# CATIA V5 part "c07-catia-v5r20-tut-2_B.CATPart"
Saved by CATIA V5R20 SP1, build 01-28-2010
Part number: Part1
Bounding box of the stored display mesh (mm): x 0 to 32, y -32 to 32, z -15 to 36
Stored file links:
  D:\v5_r20\psrt_files_downloaded\c07-catia-v5r20-prt\c07-catia-v5r20-tut-2_B.CATPart
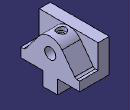
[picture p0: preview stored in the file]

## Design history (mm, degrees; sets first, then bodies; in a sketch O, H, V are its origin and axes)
Body1 (main body)
  Sketch1 on zx-plane, origin (0, 0, 0), H (-1, 0, 0), V (0, 0, 1)
    line L1 (0, 0) -> (0, 36)
    line L2 (0, 36) -> (-12, 36)
    line L3 (-12, 36) -> (-12, 10)
    line L4 (-12, 10) -> (-32, 10)
    line L5 (-32, 10) -> (-32, 0)
    point P5 (-32, 0)
    line L6 (-32, 0) -> (0, 0)
    length L1 = 36
    length L2 = 12
    length L5 = 10
    length L6 = 32
    vertical: L1 V, L3 V, L5 V
    horizontal: L2 H, L4 H, L6 H
    coincidence: P5 H
  Pad1: profile Sketch1, direction (0, 1, 0), length 32, mirrored extent
  Sketch2 on face of Pad1 from Sketch1.L5, origin (32, 0, 0), H (0, 1, 0), V (0, 0, 1)
    line L1 (0, 10) -> (27.5, 10)
    point P1 (0, 10)
    point P2 (27.5, 10)
    line L2 (27.5, 10) -> (12.8, 29.6)
    point P3 (12.8, 29.6)
    reference projected line E1 (-32, 10) -> (32, 10) from edge [face of Pad1 from Sketch1.L5 | face of Pad1 from Sketch1.L4]
    point P4 (-27.5, 10)
    point P5 (0, 10)
    line L3 (0, 10) -> (-27.5, 10)
    point P6 (-12.8, 29.6)
    line L4 (-27.5, 10) -> (-12.8, 29.6)
    arc A1 centre (0, 20) radius 16 from (12.8, 29.6) to (-12.8, 29.6) ccw
    reference projected line E2 (-32, 36) -> (32, 36) from edge [face of Pad1 from Sketch1.L3 | face of Pad1 from Sketch1.L2]
    radius A1 = 16
    distance P4 P2 = 55
    coincidence: P1 V, L1 E1, P1 P5
    horizontal: L1 H
    symmetry: P2 P4 V, P1 P5 V, L1 L3 V, P3 P6 V, L2 L4 V
    tangency: A1 L2, A1 E2
  Pad2: profile Sketch2, direction (1, 0, 0), up to the existing solid (limit type 2)
  Sketch3 on face of Pad2, origin (32, 0, 0), H (0, 1, 0), V (0, 0, 1)
    point P1 (-8, 0)
    line L1 (-8, 0) -> (8, 0)
    line L2 (8, 0) -> (8, -15)
    line L3 (8, -15) -> (-8, -15)
    line L4 (-8, -15) -> (-8, 0)
    length L3 = 16
    length L2 = 15
    distance L4 V = 8
    coincidence: P1 H
    horizontal: L1 H, L3 H
    vertical: L2 V, L4 V
  Pad3: profile Sketch3, direction (1, 0, 0), up to face of Pad1 from Sketch1.L1
  Sketch4 on zx-plane, origin (0, 0, 0), H (-1, 0, 0), V (0, 0, 1)
    point P1 (-20, 36)
    reference projected line E1 (0, 36) -> (-10, 36) from edge [face of Pad1 from Sketch1.L2 | end face of Pad1]
    distance P1 V = 20
    coincidence: P1 E1
  Sketch5 on {plane type Tangent, Support face of Pad2 from Sketch2.A1, RefPoint Sketch4.P1}, origin (20, 0, 36), H (1, 0, 0), V (0, -1, 0)
    point P1 (0, 0)
    reference projected point E1 (0, 0) from Sketch4.P1
    coincidence: E1 P1
  Hole1: placed by Sketch5, at (20, 0, 36) direction (0, 0, -1), diameter 6, depth 16, counterbore diameter 10, counterbore depth 4
  Fillet1: radius 3, on edge [face of Pad1 from Sketch1.L4 | face of Pad2 from Sketch2.L2]; edge [face of Pad2 from Sketch2.L4 | face of Pad1 from Sketch1.L4]
  Sketch6 on face of Pad3 from Sketch3.L3, origin (11.5351, 1.2048, -15), H (1, 0, 0), V (0, -1, 0)
    point P1 (-3.5351, 1.2048)
    reference projected line E1 (-11.5351, -6.7952) -> (-11.5351, 9.2048) from edge [face of Pad3 from Sketch3.L3 | end face of Pad3]
    reference projected line E2 (20.4649, -6.7952) -> (-11.5351, -6.7952) from edge [face of Pad3 from Sketch3.L3 | face of Pad3 from Sketch3.L2]
    distance P1 E1 = 8
    distance E2 P1 = 8
  Hole2: placed by Sketch6, at (8, 0, -15) direction (0, 0, 1), diameter 6, depth 16, V-bottom angle 120
  Sketch7 on face of Pad3 from Sketch3.L3, origin (26.6528, -0.5857, -15), H (1, 0, 0), V (0, -1, 0)
    point P1 (-2.6528, 0)
    reference projected line E1 (5.3472, -8.5857) -> (-26.6528, -8.5857) from edge [face of Pad3 from Sketch3.L3 | face of Pad3 from Sketch3.L2]
    reference projected point E2 (-18.6528, -0.5857) from edge
    distance E1 H = 8
    distance E2 P1 H = 16
  Hole3: placed by Sketch7, at (24, -0.5857, -15) direction (0, 0, 1), diameter 6, depth 16, V-bottom angle 120
  Sketch8 on face of Pad2, origin (32, -6.1541, 20.7645), H (0, 1, 0), V (0, 0, 1)
    point P1 (6.1541, -0.7645)
    reference projected arc E1 centre (6.1541, -0.7645) radius 16 from (18.9541, 8.8355) to (-6.6459, 8.8355) ccw from edge [face of Pad2 from Sketch2.A1 | start face of Pad2]
    concentricity: P1 E1
  Hole4: placed by Sketch8, at (32, 0, 20) direction (-1, 0, 0), diameter 12, depth 24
